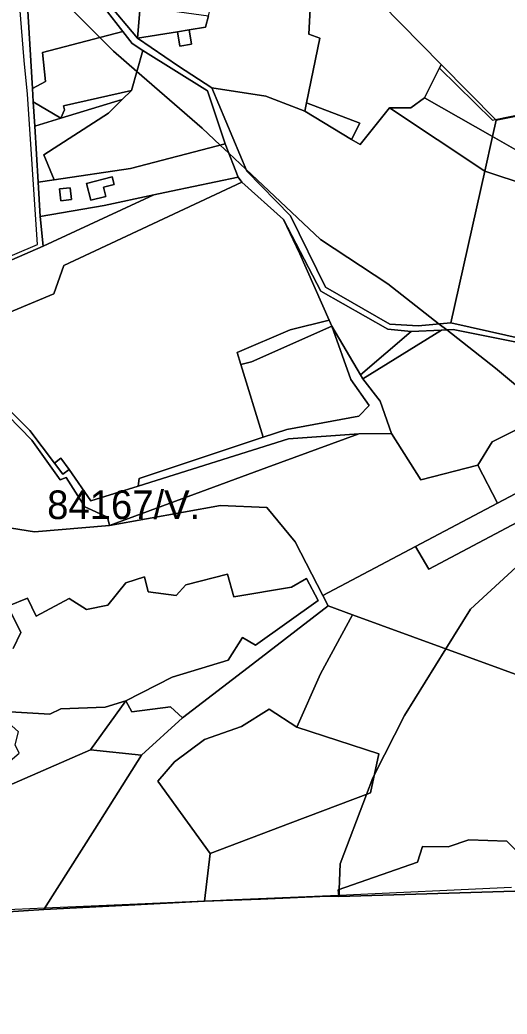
# Model space of a CAD drawing. Extents: x -477304 to -465429, y -1159113 to -1149210.
# Drawn here: x -473638 to -473382, y -1157079 to -1156558 of the extents above; entities that cross this region are included whole.
import ezdxf

# ---------------------------------------------------------------- set-up
doc = ezdxf.new("R2010")
doc.units = 0
for name, color, linetype in [('BPEJ_s', 7, 'Continuous'), ('ostatni_s', 7, 'Continuous'), ('PUPFL_s', 7, 'Continuous'), ('trav_porost_s', 7, 'Continuous')]:
    doc.layers.add(name, color=color, linetype=linetype)

msp = doc.modelspace()

# ---------------------------------------------------------------- linework, layer by layer
at = {"layer": 'BPEJ_s'}
for points in [[(-473643.25, -1156486.94), (-473518.41, -1156480.7), (-473516.73, -1156482.43), (-473514.24, -1156482.29), (-473480, -1156517.16), (-473416.9, -1156581.41), (-473417.83, -1156583.28), (-473390.1, -1156610.56), (-473388.57, -1156610.25), (-473279.83, -1156588.02), (-473134.47, -1156559.66), (-473131.42, -1156559.07), (-473116.51, -1156570.86), (-473107.84, -1156577.45), (-473073.18, -1156602.49), (-473011.71, -1156646.91), (-472993.24, -1156660.25)], [(-473643.25, -1156486.94), (-473518.41, -1156480.7), (-473516.73, -1156482.43), (-473514.24, -1156482.29), (-473480, -1156517.16), (-473416.9, -1156581.41), (-473417.83, -1156583.28), (-473390.1, -1156610.56), (-473388.57, -1156610.25), (-473279.83, -1156588.02), (-473134.47, -1156559.66), (-473131.42, -1156559.07), (-473116.51, -1156570.86), (-473107.84, -1156577.45), (-473073.18, -1156602.49), (-473011.71, -1156646.91), (-472993.24, -1156660.25)], [(-473719.53, -1156714.42), (-473628.68, -1156675.76), (-473633.88, -1156597.04), (-473635.61, -1156579.35), (-473640.28, -1156522.85)], [(-473719.53, -1156714.42), (-473628.68, -1156675.76), (-473633.88, -1156597.04), (-473635.61, -1156579.35), (-473640.28, -1156522.85)], [(-473635.3, -1156527.85), (-473595.96, -1156567.32), (-473588.8, -1156574.5), (-473576.58, -1156585.08), (-473542.33, -1156614.72), (-473532.81, -1156623.69), (-473528.4, -1156627.84), (-473519.37, -1156636.34), (-473480.26, -1156673.15), (-473444.89, -1156696.39), (-473417.98, -1156717.44), (-473414.03, -1156720.53), (-473388.37, -1156740.6), (-473362.48, -1156762.23)], [(-473362.48, -1156762.23), (-473388.37, -1156740.6), (-473414.03, -1156720.53), (-473417.98, -1156717.44), (-473444.89, -1156696.39), (-473480.26, -1156673.15), (-473519.37, -1156636.34), (-473528.4, -1156627.84), (-473532.81, -1156623.69), (-473542.33, -1156614.72), (-473576.58, -1156585.08), (-473588.8, -1156574.5), (-473595.96, -1156567.32), (-473635.3, -1156527.85)], [(-473362.36, -1156830.93), (-473401.55, -1156866.82), (-473414.49, -1156887.65), (-473436.23, -1156922.65), (-473451.98, -1156953.51), (-473452.87, -1156955.25), (-473456.16, -1156963.98), (-473469.86, -1157000.33), (-473470.41, -1157013.75), (-473470.54, -1157016.97), (-473470.76, -1157016.98), (-473529.51, -1157019.4), (-473532.78, -1157019.54), (-473541.06, -1157019.91), (-473572.16, -1157021.27), (-473624.94, -1157023.58), (-473656.43, -1157024.97)], [(-473436.23, -1156922.65), (-473414.49, -1156887.65), (-473401.55, -1156866.82), (-473362.36, -1156830.93)], [(-473380.09, -1157012.77), (-473470.54, -1157016.97), (-473470.41, -1157013.75), (-473469.86, -1157000.33), (-473456.16, -1156963.98), (-473452.87, -1156955.25), (-473451.98, -1156953.51), (-473436.23, -1156922.65)], [(-473380.09, -1157012.77), (-473470.54, -1157016.97), (-473470.76, -1157016.98), (-473529.51, -1157019.4), (-473532.78, -1157019.54), (-473541.06, -1157019.91), (-473572.16, -1157021.27), (-473624.94, -1157023.58), (-473656.43, -1157024.97)]]:
    msp.add_lwpolyline(points, dxfattribs=at)
at = {"layer": 'ostatni_s'}
for points in [[(-473592.18, -1156548.81), (-473576.19, -1156567.7), (-473554.68, -1156582.22), (-473537.28, -1156593.7), (-473518.98, -1156637.27), (-473496.02, -1156660.78), (-473477.54, -1156698.09), (-473443.95, -1156717.51), (-473429.09, -1156718.45), (-473411.86, -1156716.88), (-473362.75, -1156727.76)], [(-473367.9, -1156728.95), (-473410.73, -1156720.39), (-473416.75, -1156720.64), (-473432.73, -1156721.3), (-473444.94, -1156720.15), (-473480.01, -1156700.3), (-473499.66, -1156662.67), (-473521.49, -1156643.14), (-473523.48, -1156640.39), (-473530.29, -1156623.03), (-473539.57, -1156595.18), (-473573.41, -1156574.02), (-473579.05, -1156570.49), (-473583.95, -1156564.21), (-473593.24, -1156552.29)]]:
    msp.add_lwpolyline(points, dxfattribs=at)
for points in [[(-473547.93, -1156570.85), (-473554.06, -1156571.86), (-473555.31, -1156564.27), (-473549.17, -1156563.26)], [(-473464.01, -1156620.69), (-473488.54, -1156605.97), (-473487.55, -1156601.45), (-473459.68, -1156612.19)], [(-473600.67, -1156652.57), (-473602.93, -1156643.8), (-473589.54, -1156640.35), (-473588.53, -1156644.32), (-473594.01, -1156645.71), (-473592.78, -1156650.56)], [(-473625.81, -1156676.7), (-473627.26, -1156661.08), (-473593.73, -1156655.39), (-473567.65, -1156649.8)], [(-473617.21, -1156646.64), (-473611.56, -1156646.02), (-473610.89, -1156652.19), (-473616.54, -1156652.81)], [(-473459.29, -1156744.06), (-473432.73, -1156721.3), (-473416.75, -1156720.64), (-473458.08, -1156746.11)], [(-473377.31, -1156772.7), (-473362.19, -1156773.2), (-473352.87, -1156793.19), (-473387.39, -1156811.39), (-473397.77, -1156791.4), (-473390.19, -1156779.19)], [(-473612.09, -1156793.67), (-473615.48, -1156796.18), (-473619.83, -1156790.32), (-473616.43, -1156787.8)], [(-473558.99, -1156918.16), (-473552.65, -1156923.87), (-473574.06, -1156943.39), (-473600.93, -1156940.69), (-473582.41, -1156914.94), (-473579.22, -1156920.65)]]:
    msp.add_lwpolyline(points, close=True, dxfattribs=at)
at = {"layer": 'PUPFL_s'}
for points in [[(-473108.31, -1156497.99), (-473134.72, -1156560.25), (-473224.75, -1156578.04), (-473388.18, -1156610.65), (-473416.9, -1156581.41), (-473480, -1156517.16)], [(-473636.05, -1156515.36), (-473631.31, -1156594.03), (-473630.89, -1156600.93), (-473630.12, -1156613.77), (-473628.35, -1156643.07), (-473627.26, -1156661.08), (-473625.81, -1156676.7), (-473682.06, -1156701.08)], [(-473375.84, -1156995.2), (-473382.56, -1156988.47), (-473402.51, -1156987.86), (-473413.33, -1156991.54), (-473426.79, -1156991.26), (-473429.29, -1156999.54), (-473471.03, -1157013.97), (-473470.72, -1157017.46), (-473476.79, -1157017.41), (-473511.71, -1157018.92), (-473541.07, -1157020.01), (-473538.18, -1156994.98), (-473496.16, -1156979.07), (-473454.06, -1156963.19), (-473449.65, -1156942.65), (-473492.75, -1156928.81), (-473480.21, -1156900.79), (-473463.39, -1156869.81), (-473370.38, -1156903.75)], [(-473678.83, -1157027.86), (-473625.44, -1157024.37), (-473581.01, -1157022.08), (-473541.07, -1157020.01), (-473511.71, -1157018.92), (-473476.79, -1157017.41), (-473470.72, -1157017.46), (-473372.53, -1157014.45), (-473355.77, -1157014.32), (-473244.36, -1157010.73), (-473144.57, -1157006.56), (-473078.01, -1157005.55), (-472982.79, -1156997.22)]]:
    msp.add_lwpolyline(points, dxfattribs=at)
for points in [[(-473592.18, -1156548.81), (-473574.82, -1156551.1), (-473576.19, -1156567.7)], [(-473574.82, -1156551.1), (-473539.06, -1156555.83), (-473540.58, -1156561.85), (-473549.17, -1156563.26), (-473555.31, -1156564.27), (-473576.19, -1156567.7)], [(-473390.09, -1156619.23), (-473425.68, -1156598.98), (-473416.9, -1156581.41), (-473388.18, -1156610.65)], [(-473349.1, -1156652.23), (-473370.49, -1156630.43), (-473390.09, -1156619.23), (-473388.18, -1156610.65), (-473224.75, -1156578.04), (-473284.15, -1156660.58), (-473294.6, -1156675.11), (-473300.06, -1156673.97), (-473291.03, -1156666.31), (-473291.42, -1156660.86), (-473306.47, -1156656.24), (-473330.64, -1156656.96)], [(-473394.13, -1156637.37), (-473444.1, -1156604.09), (-473432.92, -1156604.12), (-473425.68, -1156598.98), (-473390.09, -1156619.23)], [(-473349.1, -1156652.23), (-473394.13, -1156637.37), (-473390.09, -1156619.23), (-473370.49, -1156630.43)], [(-473496.13, -1156720.47), (-473475.64, -1156715.43), (-473474.24, -1156718.58), (-473516.45, -1156737.26), (-473522.08, -1156738.59), (-473523.99, -1156732.42)], [(-473442.99, -1156774.8), (-473460.14, -1156775.02), (-473497.06, -1156777.58), (-473575.97, -1156802.37), (-473575.33, -1156798.45), (-473510.24, -1156776.82), (-473497.94, -1156772.73), (-473460.14, -1156765.69), (-473454.66, -1156760.21), (-473464.35, -1156746.58), (-473474.24, -1156718.58), (-473459.29, -1156744.06), (-473458.08, -1156746.11), (-473448.91, -1156757.89)], [(-473474.24, -1156718.58), (-473464.35, -1156746.58), (-473454.66, -1156760.21), (-473460.14, -1156765.69), (-473497.94, -1156772.73), (-473510.24, -1156776.82), (-473522.08, -1156738.59), (-473516.45, -1156737.26)], [(-473615.48, -1156796.18), (-473612.09, -1156793.67), (-473600.75, -1156810.16), (-473575.97, -1156802.37), (-473497.06, -1156777.58), (-473460.14, -1156775.02), (-473508.36, -1156792.73), (-473549.63, -1156807.91), (-473590.97, -1156823.09), (-473592.02, -1156818.75), (-473603.88, -1156813.25), (-473613.61, -1156797.97), (-473616.85, -1156799.06), (-473631.7, -1156778.3), (-473656.78, -1156752.69), (-473676.71, -1156736.56), (-473672.85, -1156734.78), (-473654.9, -1156751.2), (-473632.64, -1156773.19), (-473619.83, -1156790.32)], [(-473479.07, -1156859.72), (-473493.51, -1156831.55), (-473508.42, -1156813.61), (-473532.72, -1156812.53), (-473590.97, -1156823.09), (-473549.63, -1156807.91), (-473508.36, -1156792.73), (-473460.14, -1156775.02), (-473442.99, -1156774.8), (-473427.59, -1156799.07), (-473397.77, -1156791.4), (-473387.39, -1156811.39), (-473430.5, -1156834.12)], [(-473357.74, -1156871.05), (-473364.18, -1156890.97), (-473370.38, -1156903.75), (-473463.39, -1156869.81), (-473476.24, -1156865.24), (-473479.07, -1156859.72), (-473430.5, -1156834.12), (-473423.35, -1156845.98), (-473347.87, -1156805.93), (-473339.88, -1156826.32), (-473339.92, -1156843.97), (-473343.89, -1156849.27)], [(-473556.79, -1156946.9), (-473565.5, -1156957.08), (-473538.18, -1156994.98), (-473541.07, -1157020.01), (-473581.01, -1157022.08), (-473625.44, -1157024.37), (-473598.67, -1156982.16), (-473574.06, -1156943.39), (-473552.65, -1156923.87), (-473515.9, -1156895.68), (-473476.24, -1156865.24), (-473463.39, -1156869.81), (-473480.21, -1156900.79), (-473492.75, -1156928.81), (-473507.24, -1156919.33), (-473521.74, -1156928.37), (-473541.04, -1156935.16)], [(-473507.24, -1156919.33), (-473492.75, -1156928.81), (-473449.65, -1156942.65), (-473454.06, -1156963.19), (-473496.16, -1156979.07), (-473538.18, -1156994.98), (-473565.5, -1156957.08), (-473556.79, -1156946.9), (-473541.04, -1156935.16), (-473521.74, -1156928.37)], [(-473711.83, -1157074.99), (-473699.06, -1157060.27), (-473696.31, -1157050.73), (-473682.95, -1157033.35), (-473697.33, -1157013.67), (-473716.39, -1157028.49), (-473723.32, -1157026.58), (-473730.06, -1157032.72), (-473723.69, -1157040.12), (-473733.3, -1157046.88), (-473728.4, -1156993.75), (-473713.94, -1156987.63), (-473714.1, -1157003.71), (-473677.14, -1156999.21), (-473663.21, -1156967.68), (-473600.93, -1156940.69), (-473574.06, -1156943.39), (-473598.67, -1156982.16), (-473625.44, -1157024.37), (-473678.83, -1157027.86), (-473708.25, -1157079.15)], [(-473375.84, -1156995.2), (-473372.53, -1157014.45), (-473470.72, -1157017.46), (-473471.03, -1157013.97), (-473429.29, -1156999.54), (-473426.79, -1156991.26), (-473413.33, -1156991.54), (-473402.51, -1156987.86), (-473382.56, -1156988.47)]]:
    msp.add_lwpolyline(points, close=True, dxfattribs=at)
at = {"layer": 'trav_porost_s'}
for points in [[(-473624.07, -1156512.7), (-473607.02, -1156546.89), (-473593.24, -1156552.29), (-473583.95, -1156564.21), (-473626.1, -1156575.12), (-473624.44, -1156590.36), (-473631.31, -1156594.03), (-473636.05, -1156515.36)], [(-473425.68, -1156598.98), (-473432.92, -1156604.12), (-473444.1, -1156604.09), (-473459.46, -1156623.42), (-473464.01, -1156620.69), (-473459.68, -1156612.19), (-473487.55, -1156601.45), (-473480.62, -1156567.6), (-473486.37, -1156565.48), (-473485.38, -1156545.68), (-473480.68, -1156528.52), (-473480, -1156517.16), (-473416.9, -1156581.41)], [(-473485.38, -1156545.68), (-473486.37, -1156565.48), (-473480.62, -1156567.6), (-473487.55, -1156601.45), (-473488.54, -1156605.97), (-473509.01, -1156598), (-473537.28, -1156593.7), (-473554.68, -1156582.22), (-473576.19, -1156567.7), (-473555.31, -1156564.27), (-473554.06, -1156571.86), (-473547.93, -1156570.85), (-473549.17, -1156563.26), (-473540.58, -1156561.85), (-473539.06, -1156555.83), (-473532.68, -1156530.52), (-473521.99, -1156532.49), (-473520.02, -1156521.17), (-473480.68, -1156528.52)], [(-473573.41, -1156574.02), (-473579.44, -1156595.04), (-473615.05, -1156603.03), (-473614.57, -1156605.14), (-473616.46, -1156609.6), (-473630.89, -1156600.93), (-473631.31, -1156594.03), (-473624.44, -1156590.36), (-473626.1, -1156575.12), (-473583.95, -1156564.21), (-473579.05, -1156570.49)], [(-473530.29, -1156623.03), (-473579.97, -1156635.98), (-473620, -1156641.85), (-473625.3, -1156628.71), (-473591.38, -1156606.95), (-473584.23, -1156599.77), (-473579.44, -1156595.04), (-473573.41, -1156574.02), (-473539.57, -1156595.18)], [(-473614.57, -1156605.14), (-473615.05, -1156603.03), (-473579.44, -1156595.04), (-473584.23, -1156599.77), (-473616.46, -1156609.6)], [(-473509.01, -1156598), (-473488.54, -1156605.97), (-473464.01, -1156620.69), (-473459.46, -1156623.42), (-473444.1, -1156604.09), (-473394.13, -1156637.37), (-473411.86, -1156716.88), (-473429.09, -1156718.45), (-473443.95, -1156717.51), (-473477.54, -1156698.09), (-473496.02, -1156660.78), (-473518.98, -1156637.27), (-473537.28, -1156593.7)], [(-473630.12, -1156613.77), (-473630.89, -1156600.93), (-473616.46, -1156609.6)], [(-473616.46, -1156609.6), (-473584.23, -1156599.77), (-473591.38, -1156606.95), (-473625.3, -1156628.71), (-473620, -1156641.85), (-473628.35, -1156643.07), (-473630.12, -1156613.77)], [(-473628.35, -1156643.07), (-473620, -1156641.85), (-473579.97, -1156635.98), (-473530.29, -1156623.03), (-473523.48, -1156640.39), (-473558.64, -1156647.88), (-473567.65, -1156649.8), (-473593.73, -1156655.39), (-473627.26, -1156661.08)], [(-473343.62, -1156726.24), (-473352.51, -1156735.31), (-473362.75, -1156727.76), (-473411.86, -1156716.88), (-473394.13, -1156637.37), (-473349.1, -1156652.23), (-473330.64, -1156656.96), (-473327.39, -1156668.29), (-473300.06, -1156673.97), (-473321.55, -1156692.2), (-473323.25, -1156699.38), (-473337.31, -1156724.4)], [(-473682.06, -1156701.08), (-473625.81, -1156676.7), (-473567.65, -1156649.8), (-473558.64, -1156647.88), (-473523.48, -1156640.39), (-473521.49, -1156643.14), (-473614.92, -1156686.78), (-473620.07, -1156701.55), (-473686.39, -1156729.3), (-473672.85, -1156734.78), (-473676.71, -1156736.56), (-473692.02, -1156743.6), (-473712.78, -1156741.4), (-473746.72, -1156751.77), (-473747.42, -1156757.46), (-473762.01, -1156753.75), (-473762.61, -1156735.84), (-473722.22, -1156718.42)], [(-473686.39, -1156729.3), (-473620.07, -1156701.55), (-473614.92, -1156686.78), (-473521.49, -1156643.14), (-473499.66, -1156662.67), (-473491.08, -1156680.72), (-473475.64, -1156715.43), (-473496.13, -1156720.47), (-473523.99, -1156732.42), (-473522.08, -1156738.59), (-473510.24, -1156776.82), (-473575.33, -1156798.45), (-473575.97, -1156802.37), (-473600.75, -1156810.16), (-473612.09, -1156793.67), (-473616.43, -1156787.8), (-473619.83, -1156790.32), (-473632.64, -1156773.19), (-473654.9, -1156751.2), (-473672.85, -1156734.78)], [(-473594.01, -1156645.71), (-473588.53, -1156644.32), (-473589.54, -1156640.35), (-473602.93, -1156643.8), (-473600.67, -1156652.57), (-473592.78, -1156650.56)], [(-473617.21, -1156646.64), (-473616.54, -1156652.81), (-473610.89, -1156652.19), (-473611.56, -1156646.02)], [(-473459.29, -1156744.06), (-473474.24, -1156718.58), (-473475.64, -1156715.43), (-473491.08, -1156680.72), (-473499.66, -1156662.67), (-473480.01, -1156700.3), (-473444.94, -1156720.15), (-473432.73, -1156721.3)], [(-473367.9, -1156728.95), (-473368.26, -1156730.63), (-473370.39, -1156740.46), (-473365.78, -1156755.03), (-473362.66, -1156755.7), (-473362.4, -1156765.19), (-473377.31, -1156772.7), (-473390.19, -1156779.19), (-473397.77, -1156791.4), (-473427.59, -1156799.07), (-473442.99, -1156774.8), (-473448.91, -1156757.89), (-473458.08, -1156746.11), (-473416.75, -1156720.64), (-473410.73, -1156720.39)], [(-473347.87, -1156805.93), (-473423.35, -1156845.98), (-473430.5, -1156834.12), (-473387.39, -1156811.39), (-473352.87, -1156793.19), (-473351.02, -1156797.9), (-473350.08, -1156800.3)], [(-473645.96, -1156920.52), (-473622.25, -1156921.95), (-473616.45, -1156919.09), (-473593.29, -1156918.32), (-473582.41, -1156914.94), (-473600.93, -1156940.69), (-473663.21, -1156967.68), (-473691.66, -1156975.17), (-473703.15, -1156980.95), (-473707.36, -1156979.11), (-473681.66, -1156963.5), (-473677.34, -1156966.78), (-473654.95, -1156956.33), (-473638.27, -1156942.38), (-473640.37, -1156938.09), (-473638.75, -1156931.15), (-473645.64, -1156924.98)]]:
    msp.add_lwpolyline(points, close=True, dxfattribs=at)
for points in [[(-473656.78, -1156752.69), (-473631.7, -1156778.3), (-473616.85, -1156799.06), (-473613.61, -1156797.97), (-473603.88, -1156813.25), (-473592.02, -1156818.75), (-473590.97, -1156823.09), (-473630.36, -1156826.42), (-473655.58, -1156822.27)], [(-473655.58, -1156822.27), (-473630.36, -1156826.42), (-473590.97, -1156823.09), (-473532.72, -1156812.53), (-473508.42, -1156813.61), (-473493.51, -1156831.55), (-473479.07, -1156859.72), (-473476.24, -1156865.24), (-473515.9, -1156895.68), (-473552.65, -1156923.87), (-473558.99, -1156918.16), (-473579.22, -1156920.65), (-473582.41, -1156914.94), (-473558.02, -1156902.58), (-473528.76, -1156893.6), (-473521.1, -1156881.72), (-473514.39, -1156885.78), (-473481.53, -1156862.38), (-473487.65, -1156850.77), (-473495.48, -1156855.29), (-473525.65, -1156860.5), (-473529, -1156848.51), (-473550.93, -1156854.23), (-473555.92, -1156859.76), (-473570.68, -1156857.9), (-473572.53, -1156849.93), (-473582.44, -1156853.12), (-473591.86, -1156864.84), (-473603.07, -1156867.15), (-473612.06, -1156861.23), (-473629.46, -1156870.63), (-473633.86, -1156861.06), (-473644.25, -1156865.26), (-473637.47, -1156879.16), (-473641.42, -1156887.59)], [(-473641.42, -1156887.59), (-473637.47, -1156879.16), (-473644.25, -1156865.26), (-473633.86, -1156861.06), (-473629.46, -1156870.63), (-473612.06, -1156861.23), (-473603.07, -1156867.15), (-473591.86, -1156864.84), (-473582.44, -1156853.12), (-473572.53, -1156849.93), (-473570.68, -1156857.9), (-473555.92, -1156859.76), (-473550.93, -1156854.23), (-473529, -1156848.51), (-473525.65, -1156860.5), (-473495.48, -1156855.29), (-473487.65, -1156850.77), (-473481.53, -1156862.38), (-473514.39, -1156885.78), (-473521.1, -1156881.72), (-473528.76, -1156893.6), (-473558.02, -1156902.58), (-473582.41, -1156914.94), (-473593.29, -1156918.32), (-473616.45, -1156919.09), (-473622.25, -1156921.95), (-473645.96, -1156920.52)]]:
    msp.add_lwpolyline(points, dxfattribs=at)

# ---------------------------------------------------------------- texts
at = {"layer": 'BPEJ_s'}
msp.add_text('84167/V.', height=15, dxfattribs=at).set_placement((-473623.63, -1156819.68))

doc.saveas('drawing.dxf')
